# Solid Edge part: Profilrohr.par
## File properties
Username: bmolnar
Dokumentum tartalom típus: 0
Author: bmolnar
Last saved by: bmolnar
Revision: 93
Sűrűség: 0,000 kg/m^3
Pontosság: 0,990
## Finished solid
Body 1: solid body, 63 faces, 178 edges, 112 vertices.
  Faces by surface: cylinder 33, plane 30
  Edges by curve: line 112, circle 66
Bounding box of the edges (mm): 36.000 x 263.400 x 36.000, from (-18, -254.15, -18) to (18, 9.25, 18).
Cylindrical faces by radius (mm): R0.2 x12, R0.5 x12, R3.775 x4, R4.5 x4, R10 x1
Planar faces by outward normal: +x 7, +y 1, +z 7, -x 7, -y 1, -z 7
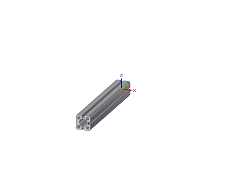
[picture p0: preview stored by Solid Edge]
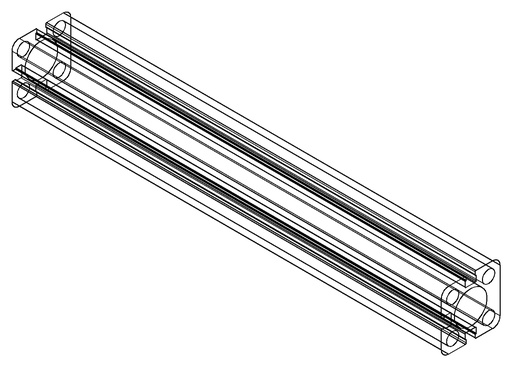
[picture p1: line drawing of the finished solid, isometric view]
